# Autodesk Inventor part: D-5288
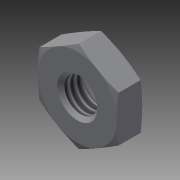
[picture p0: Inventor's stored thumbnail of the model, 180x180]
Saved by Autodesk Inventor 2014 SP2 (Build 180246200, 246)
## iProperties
Created: 2020-01
Part Number: D-5288
Material: Generic
Catalog Web Link: www.cadenas.de
Description: Mounting Nut for Original Line Cylinders-
Vendor: BIMBA
Document SubType Name: Modeling
Designer: psadmin
Manufacturer: BIMBA
Mass: 0.198468 g
Surface Area: 2.61236 cm^2
Volume: 0.198468 cm^3
Density: 1 g/cm^3
Appearance: PSOLRGB-191-191-191
Category: PARTsolutions
Company: BIMBA
Title: D-5288
Author: Cadenas PARTsolutions
PSOL_IDENT_0: {$CADENAS_DATA\23d-libs\bimba\bimba_brand\bimba_imperial\bimba_full_line\original_line_cylinders\acc
PSOL_IDENT_1: essories\mounting_nut.prj},190 {VTYP=3D},{NB=D-5288},{LINA=D-5288},{NN=Mounting Nut for Original Lin
PSOL_IDENT_2: e Cylinders},{DATE=23.12.2019 10:36:52},{GEOMDATE=10.11.2011 00:00:00},{VERSION=},{LINEID=210},{WBVA
PSOL_IDENT_3: R=MAT},{WBNUMERIC=}  {NB=D-5288},{LINA=D-5288},{KT=DUMMY},{PN=D-5288},{PN1=D-5288},{C=#10-32},{TH=UN
PSOL_IDENT_4: F},{MAT=},{MAT1='','Zinc-Plated Carbon Steel', '-SS', 'Stainless Steel'},{A=0.38},{A1=0.37500000},{B=
PSOL_IDENT_5: 0.12},{B1=0.12000000},{NDM=0.19000000},{PITCH=0.0313},{DIA=-},{DIA2=-},{DIA3=-},{DIA1=0},{DIA4=0.000
PSOL_IDENT_6: 00000},{DIA5=0.00000000},{T=-},{T2=-},{T3=-},{T1=0},{T4=0.00000000},{T5=0.00000000},{COLOR=0.75,0.75
PSOL_IDENT_7: ,0.75,0.00},{TT=0.05000000},{TO=0.20000000},{PRA=1}
NN: Mounting Nut for Original Line Cylinders
NB: D-5288
NBSYN: $PN.
LINA: D-5288
PN: D-5288
C: #10-32
MAT: Zinc-Plated Carbon Steel
A: 0.38
B: 0.12
DIA: -
T: -
SUPPLIER: BIMBA
ARTICLENO: D-5288
BOMINFO: D-5288
CREATOR: CADENAS GmbH
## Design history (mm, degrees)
sketch "Sketch_8"
  geometry: L1 (0, -3.048)-(0, 0); L2 (0, 0)-(4.763, 0); L3 (4.763, 0)-(5.715, -0.255); L4 (5.715, -0.255)-(5.715, -2.793); L5 (5.715, -2.793)-(4.763, -3.048); L6 (4.763, -3.048)-(0, -3.048); L7 (0, -3.048)-(0, 0)
  constraints: 14 end point
sketch "Sketch_10"
  geometry: L1 (-9.525, -9.525)-(9.525, -9.525); L2 (9.525, -9.525)-(9.525, 9.525); L3 (9.525, 9.525)-(-9.525, 9.525); L4 (-9.525, 9.525)-(-9.525, -9.525); L5 (-4.763, -2.75)-(0, -5.499); L6 (0, -5.499)-(4.763, -2.75); L7 (4.763, -2.75)-(4.763, 2.75); L8 (4.763, 2.75)-(0, 5.499); L9 (0, 5.499)-(-4.763, 2.75); L10 (-4.763, 2.75)-(-4.763, -2.75)
  constraints: 20 end point
revolve "Revolution1" stored, may be unused: angle "d0" = 360 deg
extrude "Extrusion1" cut sketch "Sketch_10" distance "d1" = 3.048; taper "d2" = 0 deg
sketch "Sketch_11"
  geometry: L1 (0, -3.048)-(0, 0); L2 (0, 0)-(2.413, 0); L3 (2.413, 0)-(1.984, -0.429); L4 (1.984, -0.429)-(1.984, -2.619); L5 (1.984, -2.619)-(2.413, -3.048); L6 (2.413, -3.048)-(0, -3.048); L7 (0, -3.048)-(0, 0)
  constraints: 14 end point
revolve "Revolution2" sketch "Sketch_11" stored, may be unused: angle "d3" = 360 deg
thread "Thread1" dims "d4" = 2.18948, "d5" = 0
node "NUT_XY"
node "NUT_YZ"
node "NUT_ZX"
node "NUT_X"
node "NUT_Y"
node "NUT_Z"
node "NUT_Center"
node "a1_XY"
node "a1_YZ"
node "a1_ZX"
node "a1_X"
node "a1_Y"
node "a1_Z"
node "a1_Center"
node "a2_XY"
node "a2_YZ"
node "a2_ZX"
node "a2_X"
node "a2_Y"
node "a2_Z"
node "a2_Center"
node "b1_XY"
node "b1_YZ"
node "b1_ZX"
node "b1_X"
node "b1_Y"
node "b1_Z"
node "b1_Center"
node "b2_XY"
node "b2_YZ"
node "b2_ZX"
node "b2_X"
node "b2_Y"
node "b2_Z"
node "b2_Center"
node "e_XY"
node "e_YZ"
node "e_ZX"
node "e_X"
node "e_Y"
node "e_Z"
node "e_Center"
node "ol1_XY"
node "ol1_YZ"
node "ol1_ZX"
node "ol1_X"
node "ol1_Y"
node "ol1_Z"
node "ol1_Center"
node "ol2_XY"
node "ol2_YZ"
node "ol2_ZX"
node "ol2_X"
node "ol2_Y"
node "ol2_Z"
node "ol2_Center"
node "th1_XY"
node "th1_YZ"
node "th1_ZX"
node "th1_X"
node "th1_Y"
node "th1_Z"
node "th1_Center"
node "th2_XY"
node "th2_YZ"
node "th2_ZX"
node "th2_X"
node "th2_Y"
node "th2_Z"
node "th2_Center"
body "Solid1"
other parameters: "d6" = 0, "d7" = 0, "d8" = 0
